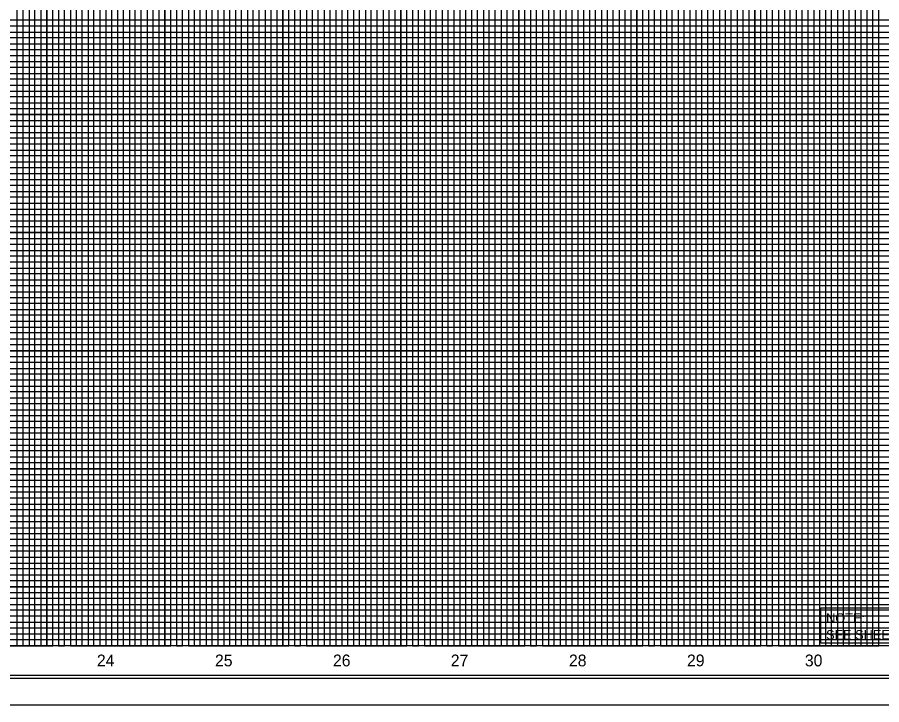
# Model space of a CAD drawing. Extents: x 2195312 to 2197214, y 76953 to 78053.
# Drawn here: x 2196054 to 2196786, y 76953 to 77535 of the extents above; entities that cross this region are included whole.
import ezdxf

# ---------------------------------------------------------------- set-up
doc = ezdxf.new("R2010")
doc.units = 0
for name, color, linetype in [('Exist Structure Minor Culvert Topo', 7, 'Continuous'), ('Old_Level_2', 7, 'Continuous'), ('Old_Level_3', 7, 'Continuous'), ('Prop North Arrow NAD83 for Plan Sheets CELL', 7, 'Continuous'), ('Scratch_Level_0', 7, 'Continuous'), ('Sheet Cutting Line CELL', 7, 'Continuous'), ('Sheet Data Field CELL', 7, 'Continuous'), ('Sheet Plan CELL', 7, 'Continuous'), ('Sheet Plot Border Inside CELL', 7, 'Continuous'), ('Sheet Plot Border Outside CELL', 7, 'Continuous'), ('Sheet Sticker Incomplete CELL', 7, 'Continuous'), ('Sheet Sticker Preliminary CELL', 7, 'Continuous')]:
    doc.layers.add(name, color=color, linetype=linetype)

msp = doc.modelspace()

# ---------------------------------------------------------------- linework, layer by layer
at = {"layer": 'Exist Structure Minor Culvert Topo'}
msp.add_lwpolyline([(2195528.73, 77352.66), (2196928.73, 77352.66), (2196928.73, 77002.66), (2195528.73, 77002.66)], close=True, dxfattribs=at)
at = {"layer": 'Old_Level_2'}
msp.add_lwpolyline([(2196991.23, 78030.21), (2195324.73, 78030.21), (2195324.73, 76975.11), (2196991.23, 76975.11)], close=True, dxfattribs=at)
at = {"layer": 'Old_Level_3'}
msp.add_lwpolyline([(2196734.53, 77034.85), (2196926.09, 77034.85), (2196926.09, 77004.85), (2196734.53, 77004.85)], close=True, dxfattribs=at)
at = {"layer": 'Scratch_Level_0'}
for points in [[(2195528.73, 77702.66), (2196928.73, 77702.66), (2196928.73, 77352.66), (2195528.73, 77352.66)], [(2195528.73, 77702.66), (2196928.73, 77702.66), (2196928.73, 77352.66), (2195528.73, 77352.66)], [(2195528.73, 77402.66), (2196928.73, 77402.66), (2196928.73, 77052.66), (2195528.73, 77052.66)]]:
    msp.add_lwpolyline(points, close=True, dxfattribs=at)
at = {"layer": 'Sheet Cutting Line CELL'}
for points in [[(2196028.73, 77002.66), (2196078.73, 77002.66), (2196078.73, 78027.66)], [(2196128.73, 78027.66), (2196128.73, 77002.66), (2196178.73, 77002.66), (2196178.73, 78027.66)], [(2196228.73, 78027.66), (2196228.73, 77002.66), (2196278.73, 77002.66), (2196278.73, 78027.66)], [(2196328.73, 78027.66), (2196328.73, 77002.66), (2196378.73, 77002.66), (2196378.73, 78027.66)], [(2196428.73, 78027.66), (2196428.73, 77002.66), (2196478.73, 77002.66), (2196478.73, 78027.66)], [(2196528.73, 78027.66), (2196528.73, 77002.66), (2196578.73, 77002.66), (2196578.73, 78027.66)], [(2196628.73, 78027.66), (2196628.73, 77002.66), (2196678.73, 77002.66), (2196678.73, 78027.66)], [(2196728.73, 78027.66), (2196728.73, 77002.66), (2196778.73, 77002.66), (2196778.73, 78027.66)], [(2196978.73, 77452.66), (2195478.73, 77452.66), (2195478.73, 77502.66), (2196978.73, 77502.66)], [(2196978.73, 77352.66), (2195478.73, 77352.66), (2195478.73, 77402.66), (2196978.73, 77402.66)], [(2196978.73, 77252.66), (2195478.73, 77252.66), (2195478.73, 77302.66), (2196978.73, 77302.66)], [(2196978.73, 77152.66), (2195478.73, 77152.66), (2195478.73, 77202.66), (2196978.73, 77202.66)], [(2196978.73, 77052.66), (2195478.73, 77052.66), (2195478.73, 77102.66), (2196978.73, 77102.66)]]:
    msp.add_lwpolyline(points, dxfattribs=at)
at = {"layer": 'Sheet Data Field CELL'}
for points in [[(2196058.73, 77002.66), (2196058.73, 78027.66)], [(2196063.73, 78027.66), (2196063.73, 77002.66), (2196068.73, 77002.66), (2196068.73, 78027.66)], [(2196073.73, 78027.66), (2196073.73, 77002.66), (2196083.73, 77002.66), (2196083.73, 78027.66)], [(2196088.73, 78027.66), (2196088.73, 77002.66), (2196088.73, 77002.66), (2196093.73, 77002.66), (2196093.73, 78027.66)], [(2196098.73, 78027.66), (2196098.73, 77002.66), (2196108.73, 77002.66), (2196108.73, 78027.66)], [(2196113.73, 78027.66), (2196113.73, 77002.66), (2196118.73, 77002.66), (2196118.73, 78027.66)], [(2196123.73, 78027.66), (2196123.73, 77002.66), (2196133.73, 77002.66), (2196133.73, 78027.66)], [(2196138.73, 78027.66), (2196138.73, 77002.66), (2196143.73, 77002.66), (2196143.73, 78027.66)], [(2196148.73, 78027.66), (2196148.73, 77002.66), (2196158.73, 77002.66), (2196158.73, 78027.66)], [(2196163.73, 78027.66), (2196163.73, 77002.66), (2196168.73, 77002.66), (2196168.73, 78027.66)], [(2196173.73, 78027.66), (2196173.73, 77002.66), (2196183.73, 77002.66), (2196183.73, 78027.66)], [(2196188.73, 78027.66), (2196188.73, 77002.66), (2196193.73, 77002.66), (2196193.73, 78027.66)], [(2196198.73, 78027.66), (2196198.73, 77002.66), (2196208.73, 77002.66), (2196208.73, 78027.66)], [(2196213.73, 78027.66), (2196213.73, 77002.66), (2196218.73, 77002.66), (2196218.73, 78027.66)], [(2196223.73, 78027.66), (2196223.73, 77002.66), (2196233.73, 77002.66), (2196233.73, 78027.66)], [(2196238.73, 78027.66), (2196238.73, 77002.66)], [(2196238.73, 77002.66), (2196243.73, 77002.66), (2196243.73, 78027.06)], [(2196248.73, 78027.06), (2196248.73, 77002.66), (2196258.73, 77002.66), (2196258.73, 78027.66)], [(2196263.73, 78027.66), (2196263.73, 77002.66), (2196268.73, 77002.66), (2196268.73, 78027.66)], [(2196273.73, 78027.66), (2196273.73, 77002.66), (2196283.73, 77002.66), (2196283.73, 78027.66)], [(2196288.73, 78027.66), (2196288.73, 77002.66), (2196293.73, 77002.66), (2196293.73, 78027.66)], [(2196298.73, 78027.66), (2196298.73, 77002.66), (2196308.73, 77002.66), (2196308.73, 78027.66)], [(2196313.73, 78027.66), (2196313.73, 77002.66), (2196318.73, 77002.66), (2196318.73, 78027.66)], [(2196323.73, 78027.66), (2196323.73, 77002.66), (2196333.73, 77002.66), (2196333.73, 78027.66)], [(2196338.73, 78027.66), (2196338.73, 77002.66), (2196343.73, 77002.66), (2196343.73, 78027.66)], [(2196348.73, 78027.66), (2196348.73, 77002.66), (2196358.73, 77002.66), (2196358.73, 78027.66)], [(2196363.73, 78027.66), (2196363.73, 77002.66), (2196368.73, 77002.66), (2196368.73, 78027.66)], [(2196373.73, 78027.66), (2196373.73, 77002.66), (2196383.73, 77002.66), (2196383.73, 78027.66)], [(2196388.73, 78027.66), (2196388.73, 77002.66), (2196393.73, 77002.66), (2196393.73, 78027.66)], [(2196398.73, 78027.66), (2196398.73, 77002.66), (2196408.73, 77002.66), (2196408.73, 78027.66)], [(2196413.73, 78027.66), (2196413.73, 77002.66), (2196418.73, 77002.66), (2196418.73, 78027.66)], [(2196423.73, 78027.66), (2196423.73, 77002.66), (2196433.73, 77002.66), (2196433.73, 78027.66)], [(2196438.73, 78027.66), (2196438.73, 77002.66), (2196443.73, 77002.66), (2196443.73, 78027.66)], [(2196448.73, 78027.66), (2196448.73, 77002.66), (2196458.73, 77002.66), (2196458.73, 78027.66)], [(2196463.73, 78027.66), (2196463.73, 77002.66), (2196468.73, 77002.66), (2196468.73, 78027.66)], [(2196473.73, 78027.66), (2196473.73, 77002.66), (2196483.73, 77002.66), (2196483.73, 78027.66)], [(2196488.73, 78027.66), (2196488.73, 77002.66), (2196493.73, 77002.66), (2196493.73, 78027.66)], [(2196498.73, 78027.66), (2196498.73, 77002.66), (2196508.73, 77002.66), (2196508.73, 78027.66)], [(2196513.73, 78027.66), (2196513.73, 77002.66), (2196518.73, 77002.66), (2196518.73, 78027.66)], [(2196523.73, 78027.66), (2196523.73, 77002.66), (2196533.73, 77002.66), (2196533.73, 78027.66)], [(2196538.73, 78027.66), (2196538.73, 77002.66), (2196543.73, 77002.66), (2196543.73, 78027.66)], [(2196548.73, 78027.66), (2196548.73, 77002.66)], [(2196548.73, 77002.66), (2196558.73, 77002.66), (2196558.73, 78027.66)], [(2196563.73, 78027.66), (2196563.73, 77002.66), (2196568.73, 77002.66), (2196568.73, 78027.66)], [(2196573.73, 78027.66), (2196573.73, 77002.66), (2196583.73, 77002.66), (2196583.73, 78027.66)], [(2196588.73, 78027.66), (2196588.73, 77002.66), (2196593.73, 77002.66), (2196593.73, 78027.66)], [(2196598.73, 78027.66), (2196598.73, 77002.66), (2196608.73, 77002.66), (2196608.73, 78027.66)], [(2196613.73, 78027.66), (2196613.73, 77002.66), (2196618.73, 77002.66), (2196618.73, 78027.66)], [(2196623.73, 78027.66), (2196623.73, 77002.66), (2196633.73, 77002.66), (2196633.73, 78027.66)], [(2196638.73, 78027.66), (2196638.73, 77002.66), (2196643.73, 77002.66), (2196643.73, 78027.66)], [(2196648.73, 78027.66), (2196648.73, 77002.66), (2196658.73, 77002.66), (2196658.73, 78027.66)], [(2196663.73, 78027.66), (2196663.73, 77002.66), (2196668.73, 77002.66), (2196668.73, 78027.66)], [(2196673.73, 78027.66), (2196673.73, 77002.66), (2196683.73, 77002.66), (2196683.73, 78027.66)], [(2196688.73, 78027.66), (2196688.73, 77002.66), (2196693.73, 77002.66), (2196693.73, 78027.66)], [(2196698.73, 78027.66), (2196698.73, 77002.66), (2196708.73, 77002.66), (2196708.73, 78027.66)], [(2196713.73, 78027.66), (2196713.73, 77002.66), (2196718.73, 77002.66), (2196718.73, 78027.66)], [(2196723.73, 78027.66), (2196723.73, 77002.66), (2196733.73, 77002.66), (2196733.73, 78027.66)], [(2196738.73, 78027.66), (2196738.73, 77002.66), (2196743.73, 77002.66), (2196743.73, 78027.66)], [(2196748.73, 78027.66), (2196748.73, 77002.66), (2196758.73, 77002.66), (2196758.73, 78027.66)], [(2196763.73, 78027.66), (2196763.73, 77002.66), (2196768.73, 77002.66), (2196768.73, 78027.66)], [(2196773.73, 78027.66), (2196773.73, 77002.66), (2196783.73, 77002.66), (2196783.73, 77866.61)], [(2196928.73, 77532.66), (2195528.73, 77532.66), (2195528.73, 77522.66), (2196928.73, 77522.66)], [(2196928.73, 77517.66), (2195528.73, 77517.66), (2195528.73, 77512.66), (2196928.73, 77512.66)], [(2196928.73, 77507.66), (2195528.73, 77507.66)], [(2195528.73, 77497.66), (2196928.73, 77497.66)], [(2196928.73, 77492.66), (2195528.73, 77492.66), (2195528.73, 77487.66), (2196928.73, 77487.66)], [(2196928.73, 77482.66), (2195528.73, 77482.66), (2195528.73, 77472.66), (2196928.73, 77472.66)], [(2196928.73, 77467.66), (2195528.73, 77467.66), (2195528.73, 77462.66), (2196928.73, 77462.66)], [(2196928.73, 77457.66), (2195528.73, 77457.66), (2195528.73, 77447.66), (2196928.73, 77447.66)], [(2196928.73, 77442.66), (2195528.73, 77442.66), (2195528.73, 77437.66), (2196928.73, 77437.66)], [(2196928.73, 77432.66), (2195528.73, 77432.66), (2195528.73, 77422.66), (2196928.73, 77422.66)], [(2196928.73, 77417.66), (2195528.73, 77417.66), (2195528.73, 77412.66), (2196928.73, 77412.66)], [(2196928.73, 77407.66), (2195528.73, 77407.66), (2195528.73, 77397.66), (2196928.73, 77397.66)], [(2196928.73, 77392.66), (2195528.73, 77392.66), (2195528.73, 77387.66), (2196928.73, 77387.66)], [(2196928.73, 77382.66), (2195528.73, 77382.66), (2195528.73, 77372.66), (2196928.73, 77372.66)], [(2196928.73, 77367.66), (2195528.73, 77367.66), (2195528.73, 77362.66), (2196928.73, 77362.66)], [(2196928.73, 77357.66), (2195528.73, 77357.66), (2195528.73, 77347.66), (2196928.73, 77347.66)], [(2196928.73, 77342.66), (2195528.73, 77342.66), (2195528.73, 77337.66), (2196928.73, 77337.66)], [(2196928.73, 77332.66), (2195528.73, 77332.66), (2195528.73, 77322.66), (2196928.73, 77322.66)], [(2196928.73, 77317.66), (2195528.73, 77317.66), (2195528.73, 77312.66), (2196928.73, 77312.66)], [(2196928.73, 77307.66), (2195528.73, 77307.66), (2195528.73, 77297.66), (2196928.73, 77297.66)], [(2196928.73, 77292.66), (2195528.73, 77292.66), (2195528.73, 77287.66), (2196928.73, 77287.66)], [(2196928.73, 77282.66), (2195528.73, 77282.66), (2195528.73, 77272.66), (2196928.73, 77272.66)], [(2196928.73, 77267.66), (2195528.73, 77267.66), (2195528.73, 77262.66), (2196928.73, 77262.66)], [(2196928.73, 77257.66), (2195528.73, 77257.66), (2195528.73, 77247.66), (2196928.73, 77247.66)], [(2196928.73, 77242.66), (2195528.73, 77242.66), (2195528.73, 77237.66), (2196928.73, 77237.66)], [(2196928.73, 77232.66), (2195528.73, 77232.66), (2195528.73, 77222.66), (2196928.73, 77222.66)], [(2196928.73, 77217.66), (2195528.73, 77217.66), (2195528.73, 77212.66), (2196928.73, 77212.66)], [(2196928.73, 77207.66), (2195528.73, 77207.66)], [(2195528.73, 77197.66), (2196928.73, 77197.66)], [(2196928.73, 77192.66), (2195528.73, 77192.66), (2195528.73, 77187.66), (2196928.73, 77187.66)], [(2196928.73, 77182.66), (2195528.73, 77182.66)], [(2195528.73, 77172.66), (2196928.73, 77172.66)], [(2196928.73, 77167.66), (2195528.73, 77167.66), (2195528.73, 77162.66), (2196928.73, 77162.66)], [(2196928.73, 77157.66), (2195528.73, 77157.66), (2195528.73, 77147.66), (2196928.73, 77147.66)], [(2196928.73, 77142.66), (2195528.73, 77142.66), (2195528.73, 77137.66), (2196928.73, 77137.66)], [(2196928.73, 77132.66), (2195528.73, 77132.66), (2195528.73, 77122.66), (2196928.73, 77122.66)], [(2196928.73, 77117.66), (2195528.73, 77117.66), (2195528.73, 77112.66), (2196928.73, 77112.66)], [(2196928.73, 77107.66), (2195528.73, 77107.66), (2195528.73, 77097.66), (2196928.73, 77097.66)], [(2196928.73, 77092.66), (2195528.73, 77092.66), (2195528.73, 77087.66), (2196928.73, 77087.66)], [(2196928.73, 77082.66), (2195528.73, 77082.66), (2195528.73, 77072.66), (2196928.73, 77072.66)], [(2196928.73, 77067.66), (2195528.73, 77067.66), (2195528.73, 77062.66), (2196928.73, 77062.66)], [(2196928.73, 77057.66), (2195528.73, 77057.66), (2195528.73, 77047.66), (2196928.73, 77047.66)], [(2196928.73, 77042.66), (2195528.73, 77042.66), (2195528.73, 77037.66), (2196928.73, 77037.66)], [(2196928.73, 77032.66), (2195528.73, 77032.66), (2195528.73, 77022.66), (2196928.73, 77022.66)], [(2196928.73, 77017.66), (2195528.73, 77017.66), (2195528.73, 77012.66), (2196928.73, 77012.66)], [(2196928.73, 77007.66), (2195528.73, 77007.66)]]:
    msp.add_lwpolyline(points, dxfattribs=at)
at = {"layer": 'Sheet Plan CELL'}
msp.add_lwpolyline([(2196995.73, 78052.66), (2195311.73, 78052.66), (2195311.73, 76952.66), (2196995.73, 76952.66)], close=True, dxfattribs=at)
at = {"layer": 'Sheet Plot Border Inside CELL'}
for p, q in [((2195478.73, 77352.66), (2196978.73, 77352.66)), ((2196978.73, 77002.66), (2195478.73, 77002.66))]:
    msp.add_line(p, q, dxfattribs=at)
msp.add_lwpolyline([(2196978.73, 78027.66), (2195478.73, 78027.66), (2195478.73, 76977.66), (2196978.73, 76977.66)], close=True, dxfattribs=at)
at = {"layer": 'Sheet Plot Border Outside CELL'}
for points in [[(2196003.73, 77002.66), (2196053.73, 77002.66), (2196053.73, 78027.66)], [(2196103.73, 78027.66), (2196103.73, 77002.66), (2196153.73, 77002.66), (2196153.73, 78027.66)], [(2196203.73, 78027.66), (2196203.73, 77002.66), (2196253.73, 77002.66), (2196253.73, 78027.66)], [(2196303.73, 78027.66), (2196303.73, 77002.66), (2196353.73, 77002.66), (2196353.73, 78027.66)], [(2196403.73, 78027.66), (2196403.73, 77002.66), (2196453.73, 77002.66), (2196453.73, 78027.66)], [(2196503.73, 78027.66), (2196503.73, 77002.66), (2196553.73, 77002.66), (2196553.73, 78027.66)], [(2196603.73, 78027.66), (2196603.73, 77002.66), (2196653.73, 77002.66), (2196653.73, 78027.66)], [(2196703.73, 78027.66), (2196703.73, 77002.66), (2196753.73, 77002.66), (2196753.73, 78027.66)], [(2196978.73, 77527.66), (2195478.73, 77527.66), (2195478.73, 77477.66), (2196978.73, 77477.66)], [(2196978.73, 77427.66), (2195478.73, 77427.66), (2195478.73, 77377.66), (2196978.73, 77377.66)], [(2196978.73, 77327.66), (2195478.73, 77327.66), (2195478.73, 77277.66), (2196978.73, 77277.66)], [(2196978.73, 77227.66), (2195478.73, 77227.66), (2195478.73, 77177.66), (2196978.73, 77177.66)], [(2196978.73, 77127.66), (2195478.73, 77127.66), (2195478.73, 77077.66), (2196978.73, 77077.66)], [(2196978.73, 77027.66), (2195478.73, 77027.66)]]:
    msp.add_lwpolyline(points, dxfattribs=at)
at = {"layer": 'Sheet Sticker Incomplete CELL'}
msp.add_line((2195311.73, 76952.66), (2196995.73, 76952.66), dxfattribs=at)
at = {"layer": 'Sheet Sticker Preliminary CELL'}
for p, q in [((2196078.73, 78027.66), (2196078.73, 77002.66)), ((2196128.73, 78027.66), (2196128.73, 77002.66)), ((2196178.73, 78027.66), (2196178.73, 77002.66)), ((2196228.73, 78027.66), (2196228.73, 77002.66)), ((2196278.73, 78027.66), (2196278.73, 77002.66)), ((2196328.73, 78027.66), (2196328.73, 77002.66)), ((2196378.73, 78027.66), (2196378.73, 77002.66)), ((2196428.73, 78027.66), (2196428.73, 77002.66)), ((2196478.73, 78027.66), (2196478.73, 77002.66)), ((2196528.73, 78027.66), (2196528.73, 77002.66)), ((2196578.73, 78027.66), (2196578.73, 77002.66)), ((2196628.73, 78027.66), (2196628.73, 77002.66)), ((2196678.73, 78027.66), (2196678.73, 77002.66)), ((2196728.73, 78027.66), (2196728.73, 77002.66)), ((2196778.73, 77002.66), (2196778.73, 77890.11)), ((2195478.73, 77502.66), (2196978.73, 77502.66)), ((2195478.73, 77452.66), (2196978.73, 77452.66)), ((2195478.73, 77402.66), (2196978.73, 77402.66)), ((2195478.73, 77352.66), (2196978.73, 77352.66)), ((2195478.73, 77302.66), (2196978.73, 77302.66)), ((2195478.73, 77252.66), (2196978.73, 77252.66)), ((2195478.73, 77202.66), (2196978.73, 77202.66)), ((2195478.73, 77152.66), (2196978.73, 77152.66)), ((2195478.73, 77102.66), (2196978.73, 77102.66)), ((2195478.73, 77052.66), (2196978.73, 77052.66))]:
    msp.add_line(p, q, dxfattribs=at)

# ---------------------------------------------------------------- texts
at = {"layer": 'Exist Structure Minor Culvert Topo'}
for s, height, p in [('NOTE:', 8.077, (2196739.1, 77022)), ('SEE SHEET 6 FOR -L1- PLAN', 8.0769, (2196739.11, 77007.86))]:
    msp.add_text(s, height=height, rotation=0.02303, dxfattribs=at).set_placement(p)
at = {"layer": 'Prop North Arrow NAD83 for Plan Sheets CELL'}
for s, p in [('24', (2196121.18, 76985.16)), ('25', (2196221.27, 76985.16)), ('26', (2196321.21, 76985.16)), ('27', (2196421.07, 76985.16)), ('28', (2196521.2, 76985.16)), ('29', (2196621.24, 76985.16)), ('30', (2196721.12, 76985.16))]:
    msp.add_text(s, height=10, dxfattribs=at).set_placement(p)

doc.saveas('drawing.dxf')
